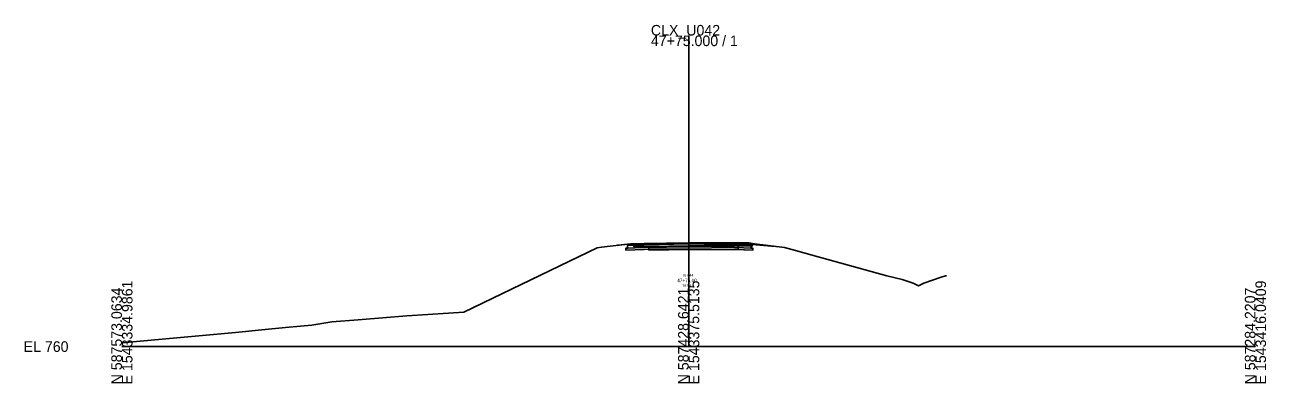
# Model space of a CAD drawing. Extents: x -26 to 1603, y -10 to 5557.
# Drawn here: x -25.7 to 302.8, y 3990.3 to 4085.2 of the extents above; entities that cross this region are included whole.
import ezdxf

# ---------------------------------------------------------------- set-up
doc = ezdxf.new("R2010")
doc.units = 0
for name, color, linetype in [('GK_Cells', 7, 'Continuous'), ('XS_P_Annotation', 7, 'Continuous'), ('XS_P_Earthwork_Shapes', 7, 'Continuous'), ('XS_P_Finished_Grade', 7, 'Continuous'), ('XS_P_Pavt_Layers', 7, 'Continuous'), ('XS_P_Pavt_Surface', 7, 'Continuous'), ('XS_P_Shoulder_Layers', 7, 'Continuous'), ('XS_P_Shoulder_Surface', 7, 'Continuous'), ('XS_P_Subgrade', 7, 'Continuous'), ('XS_X_Ground_Line', 7, 'Continuous'), ('XS_X_Pavt', 7, 'Continuous')]:
    doc.layers.add(name, color=color, linetype=linetype)

msp = doc.modelspace()

# ---------------------------------------------------------------- linework, layer by layer
at = {"layer": 'GK_Cells'}
for p, q in [((150, 4000), (150, 4082.36)), ((0, 4000), (150, 4000)), ((150, 4000), (300, 4000))]:
    msp.add_line(p, q, dxfattribs=at)
at = {"layer": 'XS_P_Earthwork_Shapes'}
for points in [[(131.18, 4026.84), (131.08, 4026.79), (132.2, 4026.92)], [(131.08, 4026.79), (132.2, 4026.92), (131.18, 4026.84)], [(131.08, 4026.79), (132.2, 4026.92), (131.18, 4026.84)], [(138.22, 4025.73), (133.35, 4025.53), (133.35, 4026.03), (133.85, 4026.05), (133.85, 4026.8), (134.18, 4026.82), (134.18, 4027.09), (132.2, 4026.92), (134.57, 4027.2), (135.3, 4027.21), (135.49, 4027.21), (135.49, 4026.46), (139.23, 4026.51), (139.49, 4026.51), (139.49, 4025.75)], [(134.18, 4027.09), (132.2, 4026.92), (134.57, 4027.2), (135.3, 4027.21), (135.49, 4027.21), (135.49, 4026.46), (139.23, 4026.51), (139.49, 4026.51), (139.49, 4025.75), (138.22, 4025.73), (133.35, 4025.53), (133.35, 4026.03), (133.85, 4026.05), (133.85, 4026.8), (134.18, 4026.82)], [(133.85, 4026.05), (133.85, 4026.8), (134.18, 4026.82), (134.18, 4027.09), (132.2, 4026.92), (134.57, 4027.2), (135.3, 4027.21), (135.49, 4027.21), (135.49, 4026.46), (139.23, 4026.51), (139.49, 4026.51), (139.49, 4025.75), (138.22, 4025.73), (133.35, 4025.53), (133.35, 4026.03)], [(150.94, 4027.45), (159.86, 4027.45), (162.36, 4027.45), (165.89, 4027.43), (166.8, 4027.31), (166.8, 4027.03), (166.18, 4027.08), (166.18, 4026.81), (166.51, 4026.8), (166.51, 4026.6), (165.89, 4026.68), (163.1, 4026.7), (162.36, 4026.7), (159.86, 4026.7), (150.94, 4026.7), (150, 4026.69), (139.49, 4026.51), (139.23, 4026.51), (135.49, 4026.46), (135.49, 4027.21), (139.23, 4027.26), (150, 4027.44)], [(135.49, 4027.21), (139.23, 4027.26), (150, 4027.44), (150.94, 4027.45), (159.86, 4027.45), (162.36, 4027.45), (165.89, 4027.43), (166.8, 4027.31), (166.8, 4027.03), (166.18, 4027.08), (166.18, 4026.81), (166.51, 4026.8), (166.51, 4026.6), (165.89, 4026.68), (163.1, 4026.7), (162.36, 4026.7), (159.86, 4026.7), (150.94, 4026.7), (150, 4026.69), (139.49, 4026.51), (139.23, 4026.51), (135.49, 4026.46)], [(135.49, 4027.21), (139.23, 4027.26), (150, 4027.44), (150.94, 4027.45), (159.86, 4027.45), (162.36, 4027.45), (165.89, 4027.43), (166.8, 4027.31), (166.8, 4027.03), (166.18, 4027.08), (166.18, 4026.81), (166.51, 4026.8), (166.51, 4026.6), (165.89, 4026.68), (163.1, 4026.7), (162.36, 4026.7), (159.86, 4026.7), (150.94, 4026.7), (150, 4026.69), (139.49, 4026.51), (139.23, 4026.51), (135.49, 4026.46)], [(150.94, 4026.7), (159.86, 4026.7), (162.36, 4026.7), (163.1, 4026.7), (163.1, 4025.7), (162.67, 4025.7), (162.14, 4025.72), (150, 4025.92), (139.49, 4025.75), (139.49, 4026.51), (150, 4026.69)], [(150, 4025.92), (139.49, 4025.75), (139.49, 4026.51), (150, 4026.69), (150.94, 4026.7), (159.86, 4026.7), (162.36, 4026.7), (163.1, 4026.7), (163.1, 4025.7), (162.67, 4025.7), (162.14, 4025.72)], [(150, 4025.92), (139.49, 4025.75), (139.49, 4026.51), (150, 4026.69), (150.94, 4026.7), (159.86, 4026.7), (162.36, 4026.7), (163.1, 4026.7), (163.1, 4025.7), (162.67, 4025.7), (162.14, 4025.72)], [(166.51, 4026.05), (167.01, 4026.03), (167.01, 4025.53), (162.67, 4025.7), (163.1, 4025.7), (163.1, 4026.7), (165.89, 4026.68), (166.51, 4026.6)], [(162.67, 4025.7), (163.1, 4025.7), (163.1, 4026.7), (165.89, 4026.68), (166.51, 4026.6), (166.51, 4026.05), (167.01, 4026.03), (167.01, 4025.53)], [(162.67, 4025.7), (163.1, 4025.7), (163.1, 4026.7), (165.89, 4026.68), (166.51, 4026.6), (166.51, 4026.05), (167.01, 4026.03), (167.01, 4025.53)], [(166.51, 4026.6), (166.8, 4026.56), (166.8, 4027.03), (166.18, 4027.08), (166.18, 4026.81), (166.51, 4026.8)], [(166.51, 4026.6), (166.8, 4026.56), (166.8, 4027.03), (166.18, 4027.08), (166.18, 4026.81), (166.51, 4026.8)], [(166.51, 4026.6), (166.8, 4026.56), (166.8, 4027.03), (166.18, 4027.08), (166.18, 4026.81), (166.51, 4026.8)], [(166.8, 4027.03), (172.99, 4026.51), (167.42, 4027.23), (166.8, 4027.31)], [(166.8, 4027.31), (167.42, 4027.23), (172.99, 4026.51), (166.8, 4027.03)], [(166.8, 4027.31), (167.42, 4027.23), (172.99, 4026.51), (166.8, 4027.03)]]:
    msp.add_lwpolyline(points, close=True, dxfattribs=at)
at = {"layer": 'XS_P_Finished_Grade'}
for p, q in [((131.18, 4026.84), (131.08, 4026.79)), ((134.18, 4027.09), (131.18, 4026.84)), ((166.18, 4027.08), (172.99, 4026.51))]:
    msp.add_line(p, q, dxfattribs=at)
at = {"layer": 'XS_P_Pavt_Layers'}
for p, q in [((133.35, 4026.03), (133.35, 4025.53)), ((133.85, 4026.8), (133.85, 4026.05)), ((134.18, 4027.09), (134.18, 4026.82)), ((150, 4027.31), (138.18, 4027.12)), ((150, 4027.17), (138.18, 4026.98)), ((150.02, 4026.42), (138.2, 4026.23)), ((150.02, 4025.92), (138.2, 4025.73)), ((149.98, 4026.42), (162.16, 4026.22)), ((149.98, 4025.92), (162.15, 4025.72)), ((150, 4027.31), (162.18, 4027.12)), ((150, 4027.17), (162.17, 4026.97)), ((166.18, 4027.08), (166.18, 4026.81)), ((166.51, 4026.8), (166.51, 4026.05)), ((167.01, 4026.03), (167.01, 4025.53))]:
    msp.add_line(p, q, dxfattribs=at)
at = {"layer": 'XS_P_Pavt_Surface'}
for q in [(138.18, 4027.25), (162.18, 4027.24)]:
    msp.add_line((150, 4027.44), q, dxfattribs=at)
at = {"layer": 'XS_P_Shoulder_Layers'}
for p, q in [((138.22, 4026.23), (133.35, 4026.03)), ((138.24, 4025.73), (133.35, 4025.53)), ((138.19, 4026.98), (133.85, 4026.8)), ((138.18, 4027.12), (134.18, 4026.96)), ((162.12, 4025.72), (167.01, 4025.53)), ((162.14, 4026.22), (167.01, 4026.03)), ((162.17, 4027.12), (166.17, 4026.96)), ((162.17, 4026.97), (166.51, 4026.8))]:
    msp.add_line(p, q, dxfattribs=at)
at = {"layer": 'XS_P_Shoulder_Surface'}
for p, q in [((138.18, 4027.25), (134.18, 4027.09)), ((162.18, 4027.24), (166.18, 4027.08))]:
    msp.add_line(p, q, dxfattribs=at)
at = {"layer": 'XS_P_Subgrade'}
msp.add_lwpolyline([(166.18, 4027.08), (166.18, 4026.81), (166.51, 4026.8), (166.51, 4026.05), (167.01, 4026.03), (167.01, 4025.53), (162.14, 4025.72), (150, 4025.92), (138.22, 4025.73), (133.35, 4025.53), (133.35, 4026.03), (133.85, 4026.05), (133.85, 4026.8), (134.18, 4026.82), (134.18, 4027.09)], dxfattribs=at)
at = {"layer": 'XS_X_Ground_Line'}
msp.add_lwpolyline([(0, 4000.97), (30.03, 4003.75), (37.93, 4004.51), (43.33, 4005.04), (47.26, 4005.42), (50.24, 4005.71), (55.52, 4006.57), (62.53, 4007.05), (75.37, 4008.1), (81, 4008.48), (90.45, 4009.11), (120.85, 4023.78), (125.77, 4026.15), (126.89, 4026.29), (134.57, 4027.2), (135.3, 4027.21), (139.23, 4027.26), (150, 4027.44), (150.94, 4027.45), (159.86, 4027.45), (162.36, 4027.45), (165.89, 4027.43), (167.42, 4027.23), (175.36, 4026.21), (178.3, 4025.4), (182.68, 4024.21), (202.42, 4018.77), (206.49, 4017.75), (209.43, 4016.82), (210.84, 4016.1), (212.21, 4016.82), (216.78, 4018.35), (217.98, 4018.74), (218.21, 4018.75)], dxfattribs=at)
at = {"layer": 'XS_X_Pavt'}
for p, q in [((135.49, 4027.21), (135.49, 4026.46)), ((135.49, 4026.46), (139.23, 4026.51)), ((139.23, 4026.51), (139.49, 4026.51)), ((139.49, 4026.51), (150, 4026.69)), ((139.49, 4026.51), (139.49, 4025.51)), ((139.49, 4025.51), (150, 4025.69)), ((150, 4026.69), (150.94, 4026.7)), ((150, 4025.69), (150.94, 4025.7)), ((150.94, 4026.7), (159.86, 4026.7)), ((150.94, 4025.7), (159.86, 4025.7)), ((159.86, 4026.7), (162.36, 4026.7)), ((159.86, 4025.7), (162.36, 4025.7)), ((162.36, 4026.7), (163.1, 4026.7)), ((162.36, 4025.7), (163.1, 4025.7)), ((163.1, 4026.7), (165.89, 4026.68)), ((163.1, 4026.7), (163.1, 4025.7)), ((165.89, 4026.68), (166.8, 4026.56)), ((166.8, 4027.31), (166.8, 4026.56))]:
    msp.add_line(p, q, dxfattribs=at)

# ---------------------------------------------------------------- texts
at = {"layer": 'GK_Cells'}
for s, p in [('CLX_U042', (140, 4082.36)), ('47+75.000 / 1', (140, 4079.56)), ('EL 760', (-26, 3998.6))]:
    msp.add_text(s, height=2.8, dxfattribs=at).set_placement(p)
for s, p in [('N 587573.0634', (0, 3990)), ('E 1543334.9861', (2.8, 3990)), ('N 587428.6421', (150, 3990)), ('E 1543375.5135', (152.8, 3990)), ('N 587284.2207', (300, 3990)), ('E 1543416.0409', (302.8, 3990))]:
    msp.add_text(s, height=2.8, rotation=90, dxfattribs=at).set_placement(p)
at = {"layer": 'XS_P_Annotation'}
for s, height, p in [('47+75.00', 0.9, (146.95, 4017.05)), ('787.44', 0.7, (148.31, 4018.55)), ('787.44', 0.7, (148.31, 4015.75))]:
    msp.add_text(s, height=height, dxfattribs=at).set_placement(p)

doc.saveas('drawing.dxf')
